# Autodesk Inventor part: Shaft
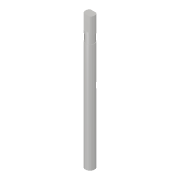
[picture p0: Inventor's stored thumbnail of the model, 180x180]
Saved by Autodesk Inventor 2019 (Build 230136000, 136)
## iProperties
Created: 2019-09
Part Number: Shaft
Material: Steel, Alloy
Document SubType Name: Modeling
Designer: Admin
Density: 7.73 g/cm^3
Appearance: Semi-Polished
Mass: 3670.35 g
Surface Area: 575.184 cm^2
Volume: 474.819 cm^3
Author: Admin
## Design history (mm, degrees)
sketch "Sketch1"
  geometry: L1 (183.329, 0)-(-164.199, 0); L2 (-0.75, -140.884)-(-0.75, 102.624); C1 r 17.45 at (-0.75, 0); 1 further point
  constraints: 4 end point, 2 point on line, 1 centre point, 1 horizontal, 1 vertical
  dimensions: "d0" = 0.75 distance from line of point (0, 0) L2; "d1" = 34.9 diameter of C1
extrude "Extrusion1" new body sketch "Sketch1" distance "d2" = 323; taper "d4" = 0 deg; dims "d3" = 186, "d5" = 0
workplane "Work Plane1"
sketch "Sketch2"
  geometry: C1 r 17.45 at (0, 0) reference; C2 r 16 at (0, 0); 1 further point
  constraints: 1 centre point, 1 coincident
  dimensions: "d7" = 32 diameter of C2
extrude "Extrusion2" cut sketch "Sketch2" distance "d8" = 30; taper "d9" = 0 deg
sketch "Sketch3"
  geometry: L1 (-30.25, 13)-(34.408, 13); L2 (-29.737, -13)-(40.353, -13); L3 (-11.641, 13)-(11.641, 13); L4 (-46.637, 0)-(59.413, 0); L5 (-11.641, -13)-(11.641, -13); A1 r 17.45 centre (0, 0) between (11.641, 13) and (-11.641, 13); A2 r 17.45 centre (0, 0) between (-11.641, -13) and (11.641, -13); 1 further point
  constraints: 10 end point, 4 point on circle, 3 horizontal, 2 centre point, 2 point on line, 2 symmetric about line, 1 collinear, 1 other
  dimensions: "d10" = 13 distance from line of point (-0.75, 0) L1; "d11" = 13 distance from line of point (-0.75, 0) L2; "d12" = 17.45 radius of A1; "d13" = 23.28111 distance of L3.end L3.start
extrude "Extrusion3" cut sketch "Sketch3" distance "d14" = 53; taper "d15" = 0 deg
workplane "Work Plane3"
sketch "Sketch5"
  geometry: L1 (76, 177.881)-(76, -129.832); L2 (98, 420.525)-(98, -398.31); L3 (0, -562.077)-(0, 584.292) reference; L4 (380.172, 12.9)-(-99.658, 12.9); L5 (-299.234, 0)-(493.406, 0) reference; L6 (98, 7.9)-(76, 7.9); L7 (98, 17.9)-(76, 17.9); L8 (103, 12.9)-(103, 17.9); L9 (103, 17.9)-(98, 17.9); L10 (71, 12.9)-(71, 17.9); L11 (-186, 17.45)-(230, 17.45) reference; L12 (71, 17.9)-(76, 17.9); A1 r 5 centre (98, 12.9) between (98, 7.9) and (103, 12.9); A2 r 5 centre (76, 12.9) between (81, 12.9) and (78.073, 17.45); A3 r 5 centre (76, 12.9) between (73.927, 17.45) and (76, 7.9); 1 further point
  constraints: 18 end point, 12 point on line, 7 point on circle, 3 centre point, 3 perpendicular, 3 vertical, 2 tangent, 1 horizontal
  dimensions: "d25" = 98 distance between parallel lines of L3 L2; "d26" = 22 distance between parallel lines of L2 L1; "d27" = 12.9 distance between parallel lines of L5 L4; "d28" = 10 diameter of A1
extrude "Extrusion5" cut sketch "Sketch5" stored distance "d30" = 53; taper "d31" = 0 deg
workaxis "Work Axis1"
feature "Move Body2"
body "Solid1"
other parameters: "d6" = -93, "d24" = 12.9, "d32" = 180 deg
